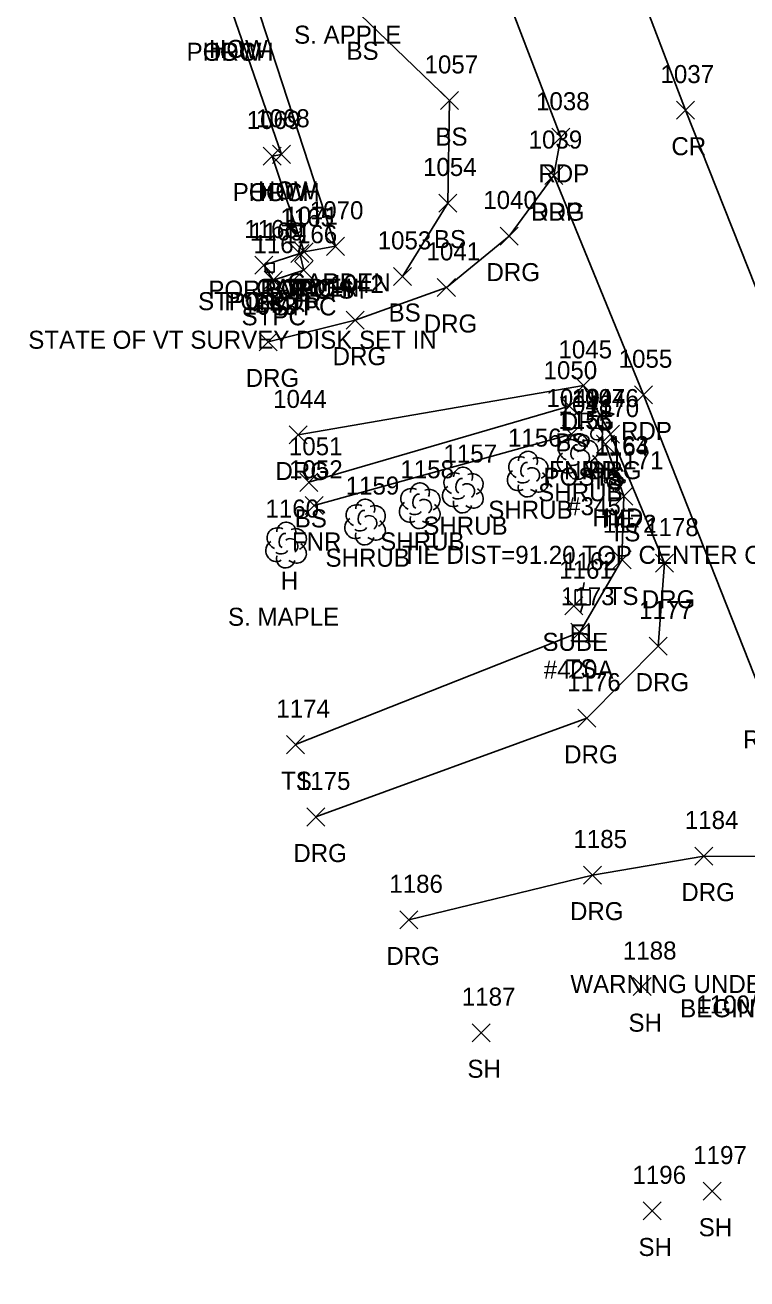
# Model space of a CAD drawing. Extents: x 1651305 to 1654558, y 539481 to 548441.
# Drawn here: x 1654091.9 to 1654172, y 544943.1 to 545082.1 of the extents above; entities that cross this region are included whole.
import ezdxf

# ---------------------------------------------------------------- set-up
doc = ezdxf.new("R2010")
doc.units = 0
for name, color, linetype in [('C_A', 7, 'Continuous'), ('C_C', 7, 'Continuous'), ('C_I', 7, 'Continuous'), ('CBP', 7, 'Continuous'), ('CPBM', 7, 'Continuous'), ('L_A', 7, 'Continuous'), ('L_C', 7, 'Continuous'), ('L_I', 7, 'Continuous'), ('L_TIC', 7, 'Continuous'), ('LAPB', 7, 'Continuous'), ('LBC', 7, 'Continuous'), ('LBF', 7, 'Continuous'), ('LELB', 7, 'Continuous'), ('LFNC', 7, 'Continuous'), ('LMB', 7, 'Continuous'), ('LPST', 7, 'Continuous'), ('LSH', 7, 'Continuous'), ('LTD', 7, 'Continuous'), ('P_A', 7, 'Continuous'), ('P_I', 7, 'Continuous'), ('P_TIC', 7, 'Continuous'), ('PET', 7, 'Continuous'), ('PRC', 7, 'Continuous'), ('R_A', 7, 'Continuous'), ('R_I', 7, 'Continuous'), ('R_TIC', 7, 'Continuous'), ('RDG', 7, 'Continuous'), ('S_C', 7, 'Continuous'), ('U_A', 7, 'Continuous'), ('U_C', 7, 'Continuous'), ('U_I', 7, 'Continuous'), ('U_TIC', 7, 'Continuous'), ('UEPT', 7, 'Continuous'), ('UWFH', 7, 'Continuous')]:
    doc.layers.add(name, color=color, linetype=linetype)

msp = doc.modelspace()

# ---------------------------------------------------------------- linework, layer by layer
at = {"layer": 'CBP'}
for radius in [0.625, 0.0833]:
    msp.add_circle((1654157.39, 545031.38), radius, dxfattribs=at)
at = {"layer": 'CPBM'}
for p, q in [((1654118.56, 545054.73), (1654118.56, 545055.73)), ((1654118.56, 545055.73), (1654119.56, 545055.73)), ((1654119.06, 545055.23), (1654119.06, 545055.23)), ((1654119.06, 545055.23), (1654119.06, 545055.23)), ((1654119.56, 545055.73), (1654119.56, 545054.73)), ((1654119.56, 545054.73), (1654118.56, 545054.73))]:
    msp.add_line(p, q, dxfattribs=at)
at = {"layer": 'L_TIC'}
for points in [[(1654138.02, 545072.76), (1654140.02, 545074.76)], [(1654140.02, 545072.76), (1654138.02, 545074.76)], [(1654118.34, 545066.6), (1654120.34, 545068.6)], [(1654120.34, 545066.6), (1654118.34, 545068.6)], [(1654118.34, 545066.6), (1654120.34, 545068.6)], [(1654120.34, 545066.6), (1654118.34, 545068.6)], [(1654119.38, 545066.79), (1654121.38, 545068.79)], [(1654121.38, 545066.79), (1654119.38, 545068.79)], [(1654137.85, 545061.39), (1654139.85, 545063.39)], [(1654139.85, 545061.39), (1654137.85, 545063.39)], [(1654121.42, 545055.79), (1654123.42, 545057.79)], [(1654123.42, 545055.79), (1654121.42, 545057.79)], [(1654121.42, 545055.79), (1654123.42, 545057.79)], [(1654123.42, 545055.79), (1654121.42, 545057.79)], [(1654121.91, 545055.99), (1654123.91, 545057.99)], [(1654123.91, 545055.99), (1654121.91, 545057.99)], [(1654121.91, 545055.99), (1654123.91, 545057.99)], [(1654123.91, 545055.99), (1654121.91, 545057.99)], [(1654125.38, 545056.59), (1654127.38, 545058.59)], [(1654127.38, 545056.59), (1654125.38, 545058.59)], [(1654117.42, 545054.51), (1654119.42, 545056.51)], [(1654119.42, 545054.51), (1654117.42, 545056.51)], [(1654117.42, 545054.51), (1654119.42, 545056.51)], [(1654119.42, 545054.51), (1654117.42, 545056.51)], [(1654121.84, 545053.93), (1654123.84, 545055.93)], [(1654123.84, 545053.93), (1654121.84, 545055.93)], [(1654132.82, 545053.25), (1654134.82, 545055.25)], [(1654134.82, 545053.25), (1654132.82, 545055.25)], [(1654118.44, 545052.83), (1654120.44, 545054.83)], [(1654120.44, 545052.83), (1654118.44, 545054.83)], [(1654151.32, 545038.85), (1654153.32, 545040.85)], [(1654153.32, 545038.85), (1654151.32, 545040.85)], [(1654151.55, 545035.77), (1654153.55, 545037.77)], [(1654153.55, 545035.77), (1654151.55, 545037.77)], [(1654155.33, 545034.65), (1654157.33, 545036.65)], [(1654157.33, 545034.65), (1654155.33, 545036.65)], [(1654122.4, 545030.42), (1654124.4, 545032.42)], [(1654124.4, 545030.42), (1654122.4, 545032.42)], [(1654157.37, 545028.87), (1654159.37, 545030.87)], [(1654159.37, 545028.87), (1654157.37, 545030.87)], [(1654122.99, 545027.86), (1654124.99, 545029.86)], [(1654124.99, 545027.86), (1654122.99, 545029.86)], [(1654157.16, 545021.82), (1654159.16, 545023.82)], [(1654159.16, 545021.82), (1654157.16, 545023.82)], [(1654152.5, 545013.79), (1654154.5, 545015.79)], [(1654154.5, 545013.79), (1654152.5, 545015.79)], [(1654120.92, 545001.33), (1654122.92, 545003.33)], [(1654122.92, 545001.33), (1654120.92, 545003.33)], [(1654159.39, 544974.5), (1654161.39, 544976.5)], [(1654161.39, 544974.5), (1654159.39, 544976.5)], [(1654141.52, 544969.39), (1654143.52, 544971.39)], [(1654143.52, 544969.39), (1654141.52, 544971.39)], [(1654167.18, 544951.82), (1654169.18, 544953.82)], [(1654169.18, 544951.82), (1654167.18, 544953.82)], [(1654160.5, 544949.63), (1654162.5, 544951.63)], [(1654162.5, 544949.63), (1654160.5, 544951.63)]]:
    msp.add_lwpolyline(points, dxfattribs=at)
at = {"layer": 'LAPB'}
msp.add_lwpolyline([(1654109.68, 545095.72), (1654113.31, 545097.61), (1654126.38, 545057.59), (1654122.91, 545056.99)], dxfattribs=at)
at = {"layer": 'LBC'}
msp.add_lwpolyline([(1654114.23, 545083.16), (1654114.94, 545083.48), (1654120.38, 545067.79), (1654119.34, 545067.6)], dxfattribs=at)
at = {"layer": 'LBF'}
for points in [[(1654119.34, 545067.6), (1654122.91, 545056.99), (1654122.42, 545056.79), (1654118.42, 545055.51)], [(1654122.42, 545056.79), (1654122.84, 545054.93), (1654119.44, 545053.83), (1654118.42, 545055.51)]]:
    msp.add_lwpolyline(points, dxfattribs=at)
at = {"layer": 'LELB'}
for points in [[(1654133.82, 545054.25), (1654138.85, 545062.39), (1654139.02, 545073.76), (1654129.15, 545083.27), (1654119.02, 545103.62), (1654091.93, 545093.63)], [(1654152.32, 545039.85), (1654123.4, 545031.42)], [(1654156.33, 545035.65), (1654158.37, 545029.87), (1654158.16, 545022.82), (1654153.5, 545014.79), (1654121.92, 545002.33)]]:
    msp.add_lwpolyline(points, dxfattribs=at)
at = {"layer": 'LFNC'}
msp.add_lwpolyline([(1654152.55, 545036.77), (1654123.99, 545028.86)], dxfattribs=at)
at = {"layer": 'LMB'}
for p, q in [((1654155.99, 545036.78), (1654155.99, 545039.38)), ((1654155.99, 545039.37), (1654157.28, 545038.99)), ((1654155.99, 545038.47), (1654157.28, 545038.98)), ((1654155.34, 545036.77), (1654155.34, 545036.77))]:
    msp.add_line(p, q, dxfattribs=at)
msp.add_circle((1654155.34, 545036.77), 0.656, dxfattribs=at)
at = {"layer": 'LPST'}
for radius in [0.625, 0.0833]:
    msp.add_circle((1654153.9, 545036.05), radius, dxfattribs=at)
at = {"layer": 'LSH'}
for p, q in [((1654153.23, 545034.32), (1654153.23, 545034.32)), ((1654153.23, 545034.32), (1654153.23, 545034.32)), ((1654147.69, 545032.38), (1654147.69, 545032.38)), ((1654147.69, 545032.38), (1654147.69, 545032.38)), ((1654140.48, 545030.61), (1654140.48, 545030.61)), ((1654140.48, 545030.61), (1654140.48, 545030.61)), ((1654135.7, 545028.87), (1654135.7, 545028.87)), ((1654135.7, 545028.87), (1654135.7, 545028.87)), ((1654129.63, 545027.06), (1654129.63, 545027.06)), ((1654129.63, 545027.06), (1654129.63, 545027.06))]:
    msp.add_line(p, q, dxfattribs=at)
for centre in [(1654153.28, 545035.75), (1654147.73, 545033.81), (1654140.53, 545032.04), (1654135.74, 545030.3), (1654129.68, 545028.5)]:
    msp.add_arc(centre, 1.05, 335.5272, 180.9563, dxfattribs=at)
for centre, major_axis, ratio, start_param, end_param in [((1654152.44, 545034.99), (1.21, -0.51), 0.895232, 1.570796, 4.712389), ((1654153.02, 545034.78), (-0.208, -0.792), 0.645439, 3.141593, 6.283185), ((1654154.27, 545034.9), (-1.14, -0.48), 0.949671, 1.570796, 4.712389), ((1654146.89, 545033.05), (1.21, -0.51), 0.895232, 1.570796, 4.712389), ((1654148.73, 545032.96), (-1.14, -0.48), 0.949671, 1.570796, 4.712389), ((1654152.15, 545033.61), (0.58, -1.04), 0.959034, 3.141593, 6.283185), ((1654153.73, 545034.15), (-0.5, 0.667), 0.989748, 3.141593, 6.283185), ((1654154.23, 545033.49), (-1.09, 0.79), 0.841452, 1.570796, 4.712389), ((1654146.6, 545031.67), (0.58, -1.04), 0.959034, 3.141593, 6.283185), ((1654147.48, 545032.84), (-0.208, -0.792), 0.645439, 3.141593, 6.283185), ((1654148.19, 545032.21), (-0.5, 0.667), 0.989748, 3.141593, 6.283185), ((1654153.23, 545032.82), (0.26, 1.06), 0.942809, 1.570796, 4.712389), ((1654152.77, 545033.57), (-0.625, -0.083), 0.423636, 0, 3.141593), ((1654139.69, 545031.27), (1.21, -0.51), 0.895232, 1.570796, 4.712389), ((1654140.27, 545031.06), (-0.208, -0.792), 0.645439, 3.141593, 6.283185), ((1654140.98, 545030.44), (-0.5, 0.667), 0.989748, 3.141593, 6.283185), ((1654141.52, 545031.19), (-1.14, -0.48), 0.949671, 1.570796, 4.712389), ((1654147.23, 545031.63), (-0.625, -0.083), 0.423636, 0, 3.141593), ((1654148.69, 545031.55), (-1.09, 0.79), 0.841452, 1.570796, 4.712389), ((1654134.9, 545029.54), (1.21, -0.51), 0.895232, 1.570796, 4.712389), ((1654135.49, 545029.33), (-0.208, -0.792), 0.645439, 3.141593, 6.283185), ((1654136.74, 545029.45), (-1.14, -0.48), 0.949671, 1.570796, 4.712389), ((1654139.4, 545029.9), (0.58, -1.04), 0.959034, 3.141593, 6.283185), ((1654140.02, 545029.86), (-0.625, -0.083), 0.423636, 0, 3.141593), ((1654141.48, 545029.77), (-1.09, 0.79), 0.841452, 1.570796, 4.712389), ((1654147.69, 545030.88), (0.26, 1.06), 0.942809, 1.570796, 4.712389), ((1654128.84, 545027.73), (1.21, -0.51), 0.895232, 1.570796, 4.712389), ((1654130.67, 545027.65), (-1.14, -0.48), 0.949671, 1.570796, 4.712389), ((1654134.61, 545028.16), (0.58, -1.04), 0.959034, 3.141593, 6.283185), ((1654136.2, 545028.7), (-0.5, 0.667), 0.989748, 3.141593, 6.283185), ((1654136.7, 545028.04), (-1.09, 0.79), 0.841452, 1.570796, 4.712389), ((1654140.48, 545029.11), (0.26, 1.06), 0.942809, 1.570796, 4.712389), ((1654128.55, 545026.36), (0.58, -1.04), 0.959034, 3.141593, 6.283185), ((1654129.42, 545027.52), (-0.208, -0.792), 0.645439, 3.141593, 6.283185), ((1654130.13, 545026.9), (-0.5, 0.667), 0.989748, 3.141593, 6.283185), ((1654130.63, 545026.23), (-1.09, 0.79), 0.841452, 1.570796, 4.712389), ((1654135.7, 545027.37), (0.26, 1.06), 0.942809, 1.570796, 4.712389), ((1654135.24, 545028.12), (-0.625, -0.083), 0.423636, 0, 3.141593), ((1654129.63, 545025.56), (0.26, 1.06), 0.942809, 1.570796, 4.712389), ((1654129.17, 545026.31), (-0.625, -0.083), 0.423636, 0, 3.141593)]:
    msp.add_ellipse(centre, major_axis=major_axis, ratio=ratio, start_param=start_param, end_param=end_param, dxfattribs=at)
at = {"layer": 'LTD'}
msp.add_line((1654120.86, 545024.51), (1654120.86, 545024.51), dxfattribs=at)
msp.add_line((1654120.86, 545024.51), (1654120.86, 545024.51), dxfattribs=at)
msp.add_arc((1654120.91, 545025.95), 1.05, 335.5272, 180.9563, dxfattribs=at)
for centre, major_axis, ratio, start_param, end_param in [((1654120.07, 545025.18), (1.21, -0.51), 0.895232, 1.570796, 4.712389), ((1654120.66, 545024.97), (-0.208, -0.792), 0.645439, 3.141593, 6.283185), ((1654121.91, 545025.1), (-1.14, -0.48), 0.949671, 1.570796, 4.712389), ((1654119.78, 545023.81), (0.58, -1.04), 0.959034, 3.141593, 6.283185), ((1654121.36, 545024.35), (-0.5, 0.667), 0.989748, 3.141593, 6.283185), ((1654121.86, 545023.68), (-1.09, 0.79), 0.841452, 1.570796, 4.712389), ((1654120.86, 545023.01), (0.26, 1.06), 0.942809, 1.570796, 4.712389), ((1654120.41, 545023.76), (-0.625, -0.083), 0.423636, 0, 3.141593)]:
    msp.add_ellipse(centre, major_axis=major_axis, ratio=ratio, start_param=start_param, end_param=end_param, dxfattribs=at)
at = {"layer": 'P_TIC'}
for points in [[(1654164.21, 545071.69), (1654166.21, 545073.69)], [(1654166.21, 545071.69), (1654164.21, 545073.69)], [(1654150.39, 545068.68), (1654152.39, 545070.68)], [(1654152.39, 545068.68), (1654150.39, 545070.68)], [(1654149.58, 545064.43), (1654151.58, 545066.43)], [(1654151.58, 545064.43), (1654149.58, 545066.43)], [(1654159.56, 545040.12), (1654161.56, 545042.12)], [(1654161.56, 545040.12), (1654159.56, 545042.12)]]:
    msp.add_lwpolyline(points, dxfattribs=at)
at = {"layer": 'PET'}
msp.add_lwpolyline([(1654112.87, 545166.54), (1654122.04, 545140.21), (1654132.62, 545111.94), (1654135.36, 545108.19), (1654138.44, 545103.48), (1654151.39, 545069.68), (1654150.58, 545065.43), (1654160.56, 545041.12), (1654174.1, 545006.91), (1654181.29, 544989.93), (1654184.89, 544987.01), (1654195.03, 544961.54), (1654207.76, 544928.16), (1654222.99, 544890.41), (1654239.03, 544850.69), (1654252.07, 544818.68), (1654270.72, 544773.03), (1654287.36, 544732.43), (1654297.76, 544708.46), (1654313.88, 544667.1), (1654319.77, 544684.6), (1654325.71, 544702.64)], dxfattribs=at)
at = {"layer": 'PRC'}
msp.add_lwpolyline([(1654126.32, 545171.74), (1654141.33, 545133.41), (1654151.93, 545107.49), (1654165.21, 545072.69), (1654175.57, 545046.61), (1654188.97, 545011.94), (1654198.02, 544989.46), (1654207.45, 544965.61), (1654220.75, 544933.07), (1654235.66, 544895.02), (1654251.31, 544856.19), (1654265.06, 544822.16), (1654283.02, 544778.21), (1654298.76, 544737.49), (1654308.6, 544712.81), (1654319.77, 544684.6)], dxfattribs=at)
at = {"layer": 'R_TIC'}
for points in [[(1654149.58, 545064.43), (1654151.58, 545066.43)], [(1654151.58, 545064.43), (1654149.58, 545066.43)], [(1654144.63, 545057.73), (1654146.63, 545059.73)], [(1654146.63, 545057.73), (1654144.63, 545059.73)], [(1654137.67, 545052.03), (1654139.67, 545054.03)], [(1654139.67, 545052.03), (1654137.67, 545054.03)], [(1654127.56, 545048.41), (1654129.56, 545050.41)], [(1654129.56, 545048.41), (1654127.56, 545050.41)], [(1654117.91, 545046), (1654119.91, 545048)], [(1654119.91, 545046), (1654117.91, 545048)], [(1654152.88, 545041.16), (1654154.88, 545043.16)], [(1654154.88, 545041.16), (1654152.88, 545043.16)], [(1654121.22, 545035.67), (1654123.22, 545037.67)], [(1654123.22, 545035.67), (1654121.22, 545037.67)], [(1654155.9, 545035.76), (1654157.9, 545037.76)], [(1654157.9, 545035.76), (1654155.9, 545037.76)], [(1654161.86, 545021.45), (1654163.86, 545023.45)], [(1654163.86, 545021.45), (1654161.86, 545023.45)], [(1654161.86, 545021.45), (1654163.86, 545023.45)], [(1654163.86, 545021.45), (1654161.86, 545023.45)], [(1654161.18, 545012.26), (1654163.18, 545014.26)], [(1654163.18, 545012.26), (1654161.18, 545014.26)], [(1654153.25, 545004.26), (1654155.25, 545006.26)], [(1654155.25, 545004.26), (1654153.25, 545006.26)], [(1654123.2, 544993.31), (1654125.2, 544995.31)], [(1654125.2, 544993.31), (1654123.2, 544995.31)], [(1654166.25, 544988.98), (1654168.25, 544990.98)], [(1654168.25, 544988.98), (1654166.25, 544990.98)], [(1654153.9, 544986.87), (1654155.9, 544988.87)], [(1654155.9, 544986.87), (1654153.9, 544988.87)], [(1654133.52, 544981.9), (1654135.52, 544983.9)], [(1654135.52, 544981.9), (1654133.52, 544983.9)]]:
    msp.add_lwpolyline(points, dxfattribs=at)
at = {"layer": 'RDG'}
for points in [[(1654150.58, 545065.43), (1654145.63, 545058.73), (1654138.67, 545053.03), (1654128.56, 545049.41), (1654118.91, 545047)], [(1654122.22, 545036.67), (1654153.88, 545042.16), (1654156.9, 545036.76), (1654162.86, 545022.45)], [(1654124.2, 544994.31), (1654154.25, 545005.26), (1654162.18, 545013.26), (1654162.86, 545022.45)], [(1654181.29, 544989.93), (1654167.25, 544989.98), (1654154.9, 544987.87), (1654134.52, 544982.9)]]:
    msp.add_lwpolyline(points, dxfattribs=at)
at = {"layer": 'U_TIC'}
for points in [[(1654151.8, 545016.73), (1654153.8, 545018.73)], [(1654153.8, 545016.73), (1654151.8, 545018.73)]]:
    msp.add_lwpolyline(points, dxfattribs=at)
at = {"layer": 'UEPT'}
for p, q in [((1654153.97, 545020.32), (1654153.8, 545019.49)), ((1654152.97, 545017.82), (1654152.97, 545019.49)), ((1654152.97, 545019.49), (1654154.63, 545019.49)), ((1654154.63, 545019.49), (1654154.63, 545017.82)), ((1654154.63, 545017.82), (1654152.97, 545017.82)), ((1654153.55, 545016.99), (1654153.8, 545017.82)), ((1654153.8, 545018.66), (1654153.8, 545018.66))]:
    msp.add_line(p, q, dxfattribs=at)
at = {"layer": 'UWFH'}
msp.add_line((1654157.36, 545031.54), (1654157.36, 545031.54), dxfattribs=at)
for centre, radius in [((1654156.36, 545031.54), 0.167), ((1654157.36, 545031.54), 0.833), ((1654158.36, 545031.54), 0.167), ((1654157.36, 545030.54), 0.167)]:
    msp.add_circle(centre, radius, dxfattribs=at)

# ---------------------------------------------------------------- texts
at = {"layer": 'C_A'}
for s, p in [('BM', (1654117.38, 545050.23)), ('TIE', (1654155.47, 545026.38))]:
    msp.add_text(s, height=2, dxfattribs=at).set_placement(p)
at = {"layer": 'C_C'}
for s, p in [('STATE OF VT SURVEY DISK SET IN', (1654092.28, 545046.23)), ('TIE DIST=91.20 TOP CENTER OF', (1654133.76, 545022.38))]:
    msp.add_text(s, height=2, dxfattribs=at).set_placement(p)
at = {"layer": 'C_I'}
for s, p in [('1169', (1654116.88, 545058.23)), ('1164', (1654155.22, 545034.38))]:
    msp.add_text(s, height=2, dxfattribs=at).set_placement(p)
at = {"layer": 'L_A'}
for s, p in [('PORCH', (1654109.85, 545078.16)), ('HOW', (1654111.62, 545078.16)), ('HOW', (1654112.33, 545078.48)), ('BS', (1654127.59, 545078.27)), ('BS', (1654137.46, 545068.76)), ('HOW', (1654117.77, 545062.79)), ('PORCH', (1654114.97, 545062.6)), ('HOW', (1654116.73, 545062.6)), ('BS', (1654137.29, 545057.39)), ('POR STPC ST', (1654112.26, 545051.79)), ('GARDEN', (1654117.58, 545051.99)), ('PORCH', (1654118.04, 545051.79)), ('PORCH', (1654118.53, 545051.99)), ('GARDEN', (1654121.05, 545052.59)), ('STPC POR', (1654111.12, 545050.51)), ('PORCH', (1654114.04, 545050.51)), ('STPC', (1654115.95, 545048.83)), ('STPC', (1654119.35, 545049.93)), ('BS', (1654132.26, 545049.25)), ('BS', (1654150.76, 545034.85)), ('POSTS', (1654149.45, 545031.05)), ('FNR', (1654150.08, 545031.77)), ('MB', (1654153.65, 545031.77)), ('SHRUB', (1654148.86, 545029.32)), ('TS', (1654154.74, 545030.65)), ('SHRUB', (1654143.32, 545027.38)), ('BS', (1654121.85, 545026.42)), ('SHRUB', (1654136.11, 545025.61)), ('FNR', (1654121.53, 545023.86)), ('SHRUB', (1654131.33, 545023.87)), ('TS', (1654156.78, 545024.87)), ('SHRUB', (1654125.26, 545022.06)), ('H', (1654120.3, 545019.51)), ('TS', (1654156.57, 545017.82)), ('TS', (1654151.91, 545009.79)), ('TS', (1654120.33, 544997.33)), ('SH', (1654158.88, 544970.5)), ('SH', (1654141.01, 544965.39)), ('SH', (1654166.67, 544947.82)), ('SH', (1654159.99, 544945.63))]:
    msp.add_text(s, height=2, dxfattribs=at).set_placement(p)
at = {"layer": 'L_C'}
for s, p in [('S. APPLE', (1654121.78, 545080.06)), ('#345', (1654152.08, 545027.77)), ('S. MAPLE', (1654114.44, 545015.51))]:
    msp.add_text(s, height=2, dxfattribs=at).set_placement(p)
at = {"layer": 'L_I'}
for s, p in [('1057', (1654136.25, 545076.76)), ('1069', (1654116.52, 545070.6)), ('1069', (1654116.52, 545070.6)), ('1068', (1654117.56, 545070.79)), ('1054', (1654136.08, 545065.39)), ('1071', (1654120.7, 545059.99)), ('1071', (1654120.7, 545059.99)), ('1070', (1654123.52, 545060.59)), ('1168', (1654116.24, 545058.51)), ('1168', (1654116.24, 545058.51)), ('1165', (1654120.25, 545059.79)), ('1165', (1654120.25, 545059.79)), ('1166', (1654120.61, 545057.93)), ('1053', (1654131.05, 545057.25)), ('1167', (1654117.26, 545056.83)), ('1050', (1654149.46, 545042.85)), ('1049', (1654149.77, 545039.77)), ('1048', (1654151.13, 545039.05)), ('1047', (1654152.57, 545039.77)), ('1170', (1654154.11, 545038.65)), ('1155', (1654151.11, 545037.32)), ('1156', (1654145.51, 545035.38)), ('1051', (1654121.2, 545034.42)), ('1157', (1654138.35, 545033.61)), ('1171', (1654156.81, 545032.87)), ('1052', (1654121.22, 545031.86)), ('1158', (1654133.57, 545031.87)), ('1159', (1654127.5, 545030.06)), ('1160', (1654118.6, 545027.51)), ('1172', (1654156.04, 545025.82)), ('1173', (1654151.38, 545017.79)), ('1174', (1654119.8, 545005.33)), ('1188', (1654158.26, 544978.5)), ('1187', (1654140.39, 544973.39)), ('1197', (1654166.06, 544955.82)), ('1196', (1654159.32, 544953.63))]:
    msp.add_text(s, height=2, dxfattribs=at).set_placement(p)
at = {"layer": 'P_A'}
for s, p in [('CR', (1654163.64, 545067.69)), ('RDP', (1654148.88, 545064.68)), ('RDP', (1654148.07, 545060.43)), ('RDP', (1654158.05, 545036.12)), ('RDP', (1654171.59, 545001.91))]:
    msp.add_text(s, height=2, dxfattribs=at).set_placement(p)
at = {"layer": 'P_I'}
for s, p in [('1037', (1654162.43, 545075.69)), ('1038', (1654148.62, 545072.68)), ('1039', (1654147.8, 545068.43)), ('1055', (1654157.79, 545044.12))]:
    msp.add_text(s, height=2, dxfattribs=at).set_placement(p)
at = {"layer": 'R_A'}
for p in [(1654148.07, 545060.43), (1654143.12, 545053.73), (1654136.16, 545048.03), (1654126.05, 545044.41), (1654116.4, 545042), (1654151.37, 545037.16), (1654119.71, 545031.67), (1654154.39, 545031.76), (1654160.35, 545017.45), (1654160.35, 545017.45), (1654159.67, 545008.26), (1654151.74, 545000.26), (1654121.69, 544989.31), (1654164.74, 544984.98), (1654152.39, 544982.87), (1654132.01, 544977.9)]:
    msp.add_text('DRG', height=2, dxfattribs=at).set_placement(p)
at = {"layer": 'R_I'}
for s, p in [('1039', (1654147.8, 545068.43)), ('1040', (1654142.77, 545061.73)), ('1041', (1654136.47, 545056.03)), ('1042', (1654125.79, 545052.41)), ('1043', (1654116.14, 545050)), ('1045', (1654151.11, 545045.16)), ('1044', (1654119.45, 545039.67)), ('1046', (1654154.07, 545039.76)), ('1178', (1654160.73, 545025.45)), ('1178', (1654160.73, 545025.45)), ('1177', (1654160.06, 545016.26)), ('1176', (1654152.07, 545008.26)), ('1175', (1654122.08, 544997.31)), ('1184', (1654165.13, 544992.98)), ('1185', (1654152.77, 544990.87)), ('1186', (1654132.34, 544985.9))]:
    msp.add_text(s, height=2, dxfattribs=at).set_placement(p)
at = {"layer": 'S_C'}
for s, p in [('WARNING UNDERGROUND TELEPHONE', (1654152.43, 544974.79)), ('1100/0904/0342', (1654166.4, 544972.52)), ('BEGIN NO PARKING', (1654164.61, 544972.1))]:
    msp.add_text(s, height=2, dxfattribs=at).set_placement(p)
at = {"layer": 'U_A'}
for s, p in [('HYD', (1654154.88, 545026.54)), ('SUBE', (1654149.33, 545012.73)), ('EL', (1654152.34, 545013.66))]:
    msp.add_text(s, height=2, dxfattribs=at).set_placement(p)
at = {"layer": 'U_C'}
msp.add_text('#420A', height=2, dxfattribs=at).set_placement((1654149.48, 545009.66))
at = {"layer": 'U_I'}
for s, p in [('1163', (1654155.19, 545034.54)), ('1162', (1654151.63, 545021.66)), ('1161', (1654151.19, 545020.73))]:
    msp.add_text(s, height=2, dxfattribs=at).set_placement(p)

doc.saveas('drawing.dxf')
